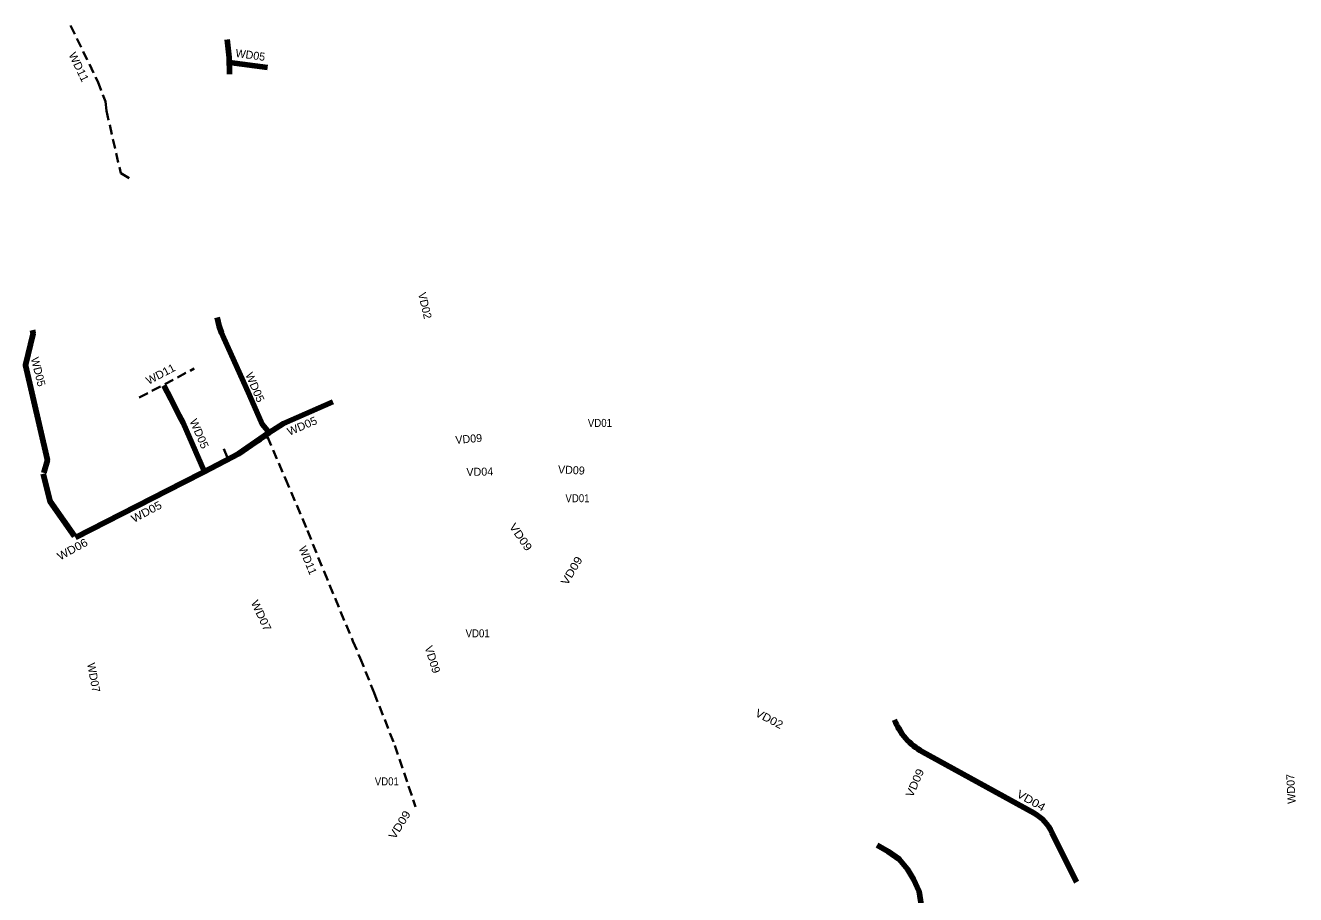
# Model space of a CAD drawing. Extents: x -650082 to -644047, y -1073134 to -1066669.
# Drawn here: x -648760 to -645586, y -1068842 to -1066669 of the extents above; entities that cross this region are included whole.
import ezdxf

# ---------------------------------------------------------------- set-up
doc = ezdxf.new("R2010")
doc.units = 0
doc.header["$LTSCALE"] = 8
doc.linetypes.add('MEDIUM_DASHED', pattern=[4.5, 3, -1.5])
for name, color, linetype in [('1', 7, 'Continuous'), ('14', 7, 'Continuous'), ('2', 7, 'Continuous'), ('4', 7, 'Continuous'), ('5', 7, 'Continuous'), ('6', 7, 'Continuous'), ('7', 7, 'Continuous'), ('9', 7, 'Continuous')]:
    doc.layers.add(name, color=color, linetype=linetype)
for name, color, linetype, lineweight in [('11', 7, 'Continuous', 106), ('13', 7, 'MEDIUM_DASHED', 35), ('47', 7, 'Continuous', 106)]:
    doc.layers.add(name, color=color, linetype=linetype, lineweight=lineweight)

msp = doc.modelspace()

# ---------------------------------------------------------------- linework, layer by layer
at = {"layer": '11'}
for p, q in [((-646518.278, -1068484.783), (-646239.17, -1068638.65)), ((-646195.455, -1068687.016), (-646134.093, -1068810.478))]:
    msp.add_line(p, q, dxfattribs=at)
msp.add_lwpolyline([(-646581.274, -1069162.086), (-646543.734, -1069031.454), (-646526.307, -1068970.81), (-646520.034, -1068926.895), (-646519.124, -1068882.525), (-646527.13, -1068833.717), (-646541.089, -1068803.463), (-646555.823, -1068777.863), (-646576.76, -1068753.039), (-646603.929, -1068734.295), (-646632.204, -1068718.474)], dxfattribs=at)
for centre, radius, start, end in [((-646447.332, -1068351.964), 150.58, 200.6496, 241.891), ((-646287.447, -1068726.224), 100, 23.08426, 61.13296)]:
    msp.add_arc(centre, radius, start, end, dxfattribs=at)
at = {"layer": '13'}
msp.add_line((-648475.967, -1067599.594), (-648338.66, -1067527.2), dxfattribs=at)
for points in [[(-648647.496, -1066669.346), (-648579.736, -1066809.705), (-648560.474, -1066859.378), (-648557.753, -1066883.158), (-648521.948, -1067038.793), (-648497.158, -1067053.043)], [(-648264.598, -1067727.614), (-648252.736, -1067757.259), (-648155.436, -1067697.673), (-648110.6, -1067802.59), (-648055.22, -1067932.18), (-648014.17, -1068034.51), (-647986.62, -1068101.02), (-647941.71, -1068208.14), (-647923.95, -1068250.62), (-647888.92, -1068337.51), (-647837.19, -1068468.84), (-647785.355, -1068622.544)]]:
    msp.add_lwpolyline(points, dxfattribs=at)
at = {"layer": '47'}
msp.add_line((-648250.646, -1066761.805), (-648155.644, -1066774.286), dxfattribs=at)
for points in [[(-648255.756, -1066704.635), (-648250.791, -1066749.246), (-648250.308, -1066790.948)], [(-648280.799, -1067399.829), (-648276.458, -1067421.144), (-648270.075, -1067437.427), (-648264.51, -1067450.68), (-648249.006, -1067485.873), (-648200.759, -1067593.281), (-648168.435, -1067666.153), (-648150.996, -1067687.099)], [(-648742.866, -1067431.082), (-648741.14, -1067439.225), (-648760.37, -1067518.466), (-648705.539, -1067755.758), (-648713.989, -1067787.686)], [(-648414.419, -1067569.399), (-648397.13, -1067602.97), (-648382.03, -1067632.31), (-648376.02, -1067643.98), (-648366.45, -1067662.56), (-648312.613, -1067785.188)], [(-648635.024, -1067949.253), (-648365.832, -1067812.108), (-648315.36, -1067786.394), (-648228.068, -1067739.85), (-648151.632, -1067687.45), (-648115.068, -1067664.278), (-647992.06, -1067610.462)], [(-648715.867, -1067790.503), (-648698.498, -1067859.523), (-648637.584, -1067945.635)]]:
    msp.add_lwpolyline(points, dxfattribs=at)

# ---------------------------------------------------------------- texts
at = {"layer": '1', "width": 0.9}
for p in [(-647354.73, -1067672.938), (-647410.82, -1067861.136), (-647660.302, -1068198.804), (-647887.323, -1068568.836)]:
    msp.add_text('VD01', height=20, rotation=0.083, dxfattribs=at).set_placement(p)
at = {"layer": '14', "width": 1.05}
for rotation, p in [(295.942, (-648653.093, -1066742.467)), (27.775, (-648452.389, -1067567.821))]:
    msp.add_text('WD11', height=20, rotation=rotation, dxfattribs=at).set_placement(p)
at = {"layer": '14'}
msp.add_text('WD11', height=20, rotation=292.311, dxfattribs=at).set_placement((-648077.911, -1067975.767))
at = {"layer": '2'}
msp.add_text('VD02', height=20, rotation=283.284, dxfattribs=at).set_placement((-647779.255, -1067339.494))
at = {"layer": '2', "width": 1.1}
msp.add_text('VD02', height=20, rotation=332.288, dxfattribs=at).set_placement((-646938.71, -1068394.329))
at = {"layer": '4'}
msp.add_text('VD04', height=20, rotation=1.14, dxfattribs=at).set_placement((-647658.076, -1067795.501))
at = {"layer": '4', "width": 1.15}
msp.add_text('VD04', height=20, rotation=330.29, dxfattribs=at).set_placement((-646285.411, -1068596.436))
at = {"layer": '5'}
for rotation, p in [(352.056, (-648236.269, -1066747.9)), (284.099, (-648747.005, -1067501.574))]:
    msp.add_text('WD05', height=20, rotation=rotation, dxfattribs=at).set_placement(p)
for rotation, width, p in [(293.365, 1.05, (-648211.332, -1067541.923)), (293.365, 1.05, (-648350.624, -1067658.036)), (23.241, 1.05, (-648100.74, -1067695.188)), (27.999, 1.1, (-648489.178, -1067912.995))]:
    msp.add_text('WD05', height=20, rotation=rotation, dxfattribs=dict(at, width=width)).set_placement(p)
at = {"layer": '6', "width": 1.1}
msp.add_text('WD06', height=20, rotation=28.611, dxfattribs=at).set_placement((-648673.978, -1068006.987))
at = {"layer": '7', "width": 1.1}
msp.add_text('WD07', height=20, rotation=295.111, dxfattribs=at).set_placement((-648197.555, -1068111.736))
at = {"layer": '7'}
for rotation, p in [(280.588, (-648606.359, -1068264.679)), (93.043, (-645585.871, -1068614.132))]:
    msp.add_text('WD07', height=20, rotation=rotation, dxfattribs=at).set_placement(p)
at = {"layer": '9'}
for rotation, p in [(4.598, (-647685.156, -1067715.389)), (356.921, (-647429.913, -1067788.745))]:
    msp.add_text('VD09', height=20, rotation=rotation, dxfattribs=at).set_placement(p)
for rotation, width, p in [(304.68, 1.15, (-647552.617, -1067922.041)), (59.386, 1.15, (-647406.292, -1068070.573)), (287.301, 1.05, (-647762.827, -1068223.473)), (66.391, 1.1, (-646543.229, -1068600.337)), (58.192, 1.15, (-647837.113, -1068705.38))]:
    msp.add_text('VD09', height=20, rotation=rotation, dxfattribs=dict(at, width=width)).set_placement(p)

doc.saveas('drawing.dxf')
